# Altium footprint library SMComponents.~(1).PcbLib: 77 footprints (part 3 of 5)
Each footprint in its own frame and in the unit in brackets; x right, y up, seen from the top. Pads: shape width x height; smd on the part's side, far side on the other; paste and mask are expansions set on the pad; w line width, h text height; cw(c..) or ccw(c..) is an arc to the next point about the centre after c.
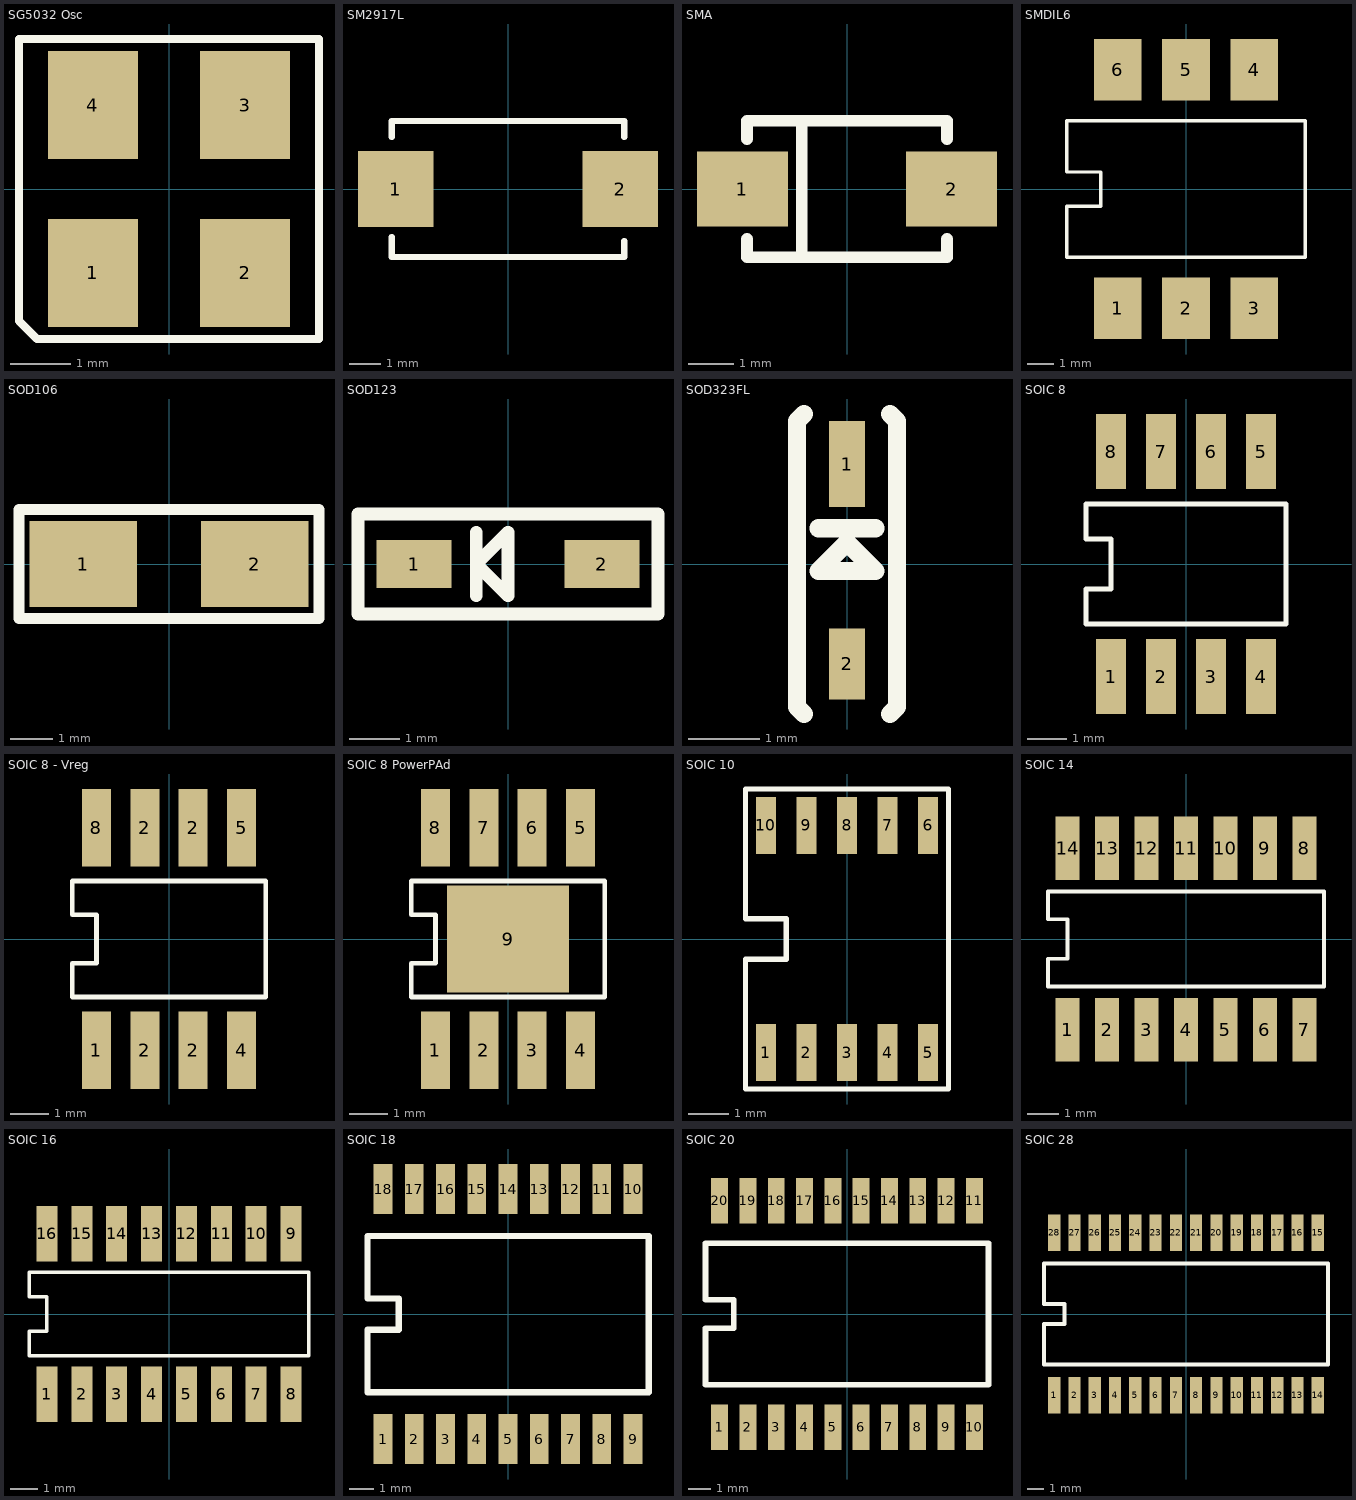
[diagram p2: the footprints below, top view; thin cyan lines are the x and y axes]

## SG5032 Osc [mm] "Epsom SG5032 oscilator"
height 1.5
pads (4):
  rect 1.5x1.8 smd: 1(-1.27,-1.4) 2(1.27,-1.4) 3(1.27,1.4) 4(-1.27,1.4)
Top Overlay:
  lines w0.127: -2.5,-2.2 -2.2,-2.5 2.5,-2.5 2.5,2.5 -2.5,2.5 -2.5,-2.2

## SM2917L [mm] "2917 for hand soldering"
pads (2):
  rect 2.4x2.4 smd: 1(-3.556,0) 2(3.556,0)
Top Overlay:
  lines w0.2: -3.683,-1.524 -3.683,-2.159 3.683,-2.159 3.683,-1.651 ; -3.683,1.651 -3.683,2.159 3.683,2.159 3.683,1.651

## SMA [mm] "SMA Diode"
height 2.65
pads (2):
  rect 2x1.65 smd: 1(-2.3,0) 2(2.3,0)
Top Overlay:
  lines w0.254: -2.2,-1.1 -2.2,-1.5 2.2,-1.5 2.2,-1.1 ; -2.2,1.1 -2.2,1.5 2.2,1.5 2.2,1.1 ; -1,-1.5 -1,1.5

## SMDIL6 [mil] "DIL6 modified to be SM"
height 200
pads (6):
  rect 70x90 smd: 1(-100,-175) 2(0,-175) 3(100,-175) 4(100,175) 5(0,175) 6(-100,175)
Top Overlay:
  lines w5: -175,-100 175,-100 175,100 -175,100 -175,25 -125,25 -125,-25 -175,-25 -175,-100

## SOD106 [mm] "SOD106 (also SOD123 etc)"
height 2
pads (2):
  rect 2.5x2 smd: 1(-2,0) 2(2,0)
Top Overlay:
  lines w0.254: -3.5,-1.27 -3.5,1.27 3.5,1.27 3.5,-1.27 -3.5,-1.27

## SOD123 [mm] "SOD123 Diode (500mW Zener etc)"
height 2
pads (2):
  rect 1.5x0.95 smd: 1(-1.875,0) 2(1.875,0)
Top Overlay:
  lines w0.254: -0.635,-0.635 -0.635,0.635 ; -3,-1 3,-1 3,1 -3,1 -3,-1 ; -0.635,0 0,-0.635 0,0.635 -0.635,0

## SOD323FL [mm]
height 1.1
pads (2):
  rect 0.5x1.2 smd: 1(0,1.4)
  rect 0.5x1 smd: 2(0,-1.4)
Top Overlay:
  lines w0.254: -0.6,-2.1 -0.7,-2 -0.7,2 -0.6,2.1 ; -0.4,0.5 0.4,0.5 ; 0.6,2.1 0.7,2 0.7,-2 0.6,-2.1 ; -0.6,2.1 -0.6,2.1 ; 0.6,-2.1 0.6,-2.1 ; -0.4,-0.1 0.4,-0.1 0,0.3 -0.4,-0.1

## SOIC 8 [mil] "SOIC 8"
height 70.87
pads (8):
  rect 30x75 smd: 1(-75,-112.5) 2(-25,-112.5) 3(25,-112.5) 4(75,-112.5) 5(75,112.5) 6(25,112.5) 7(-25,112.5) 8(-75,112.5)
Top Overlay:
  lines w5: -100,-60 -100,-25 -75,-25 -75,25 -100,25 -100,60 100,60 100,-60 -100,-60

## SOIC 8 - Vreg [mil] "SOIC 8 Special for 78Lxx and 79lXX"
height 70.87
pads (8):
  rect 30x80 smd: 1(-75,-115) 2(-25,-115) 2(-25,115) 2(25,-115) 2(25,115) 4(75,-115) 5(75,115) 8(-75,115)
Top Overlay:
  lines w5: -100,-60 -100,-25 -75,-25 -75,25 -100,25 -100,60 100,60 100,-60 -100,-60

## SOIC 8 PowerPAd [mil] "SOIC 8 with pad under device (heatsink)"
height 70.87
pads (9):
  rect 30x80 smd: 1(-75,-115) 2(-25,-115) 3(25,-115) 4(75,-115) 5(75,115) 6(25,115) 7(-25,115) 8(-75,115)
  rect 125.98x110.24 smd: 9(0,0)
Top Overlay:
  lines w5: -100,-60 100,-60 100,60 -100,60 -100,25 -75,25 -75,-25 -100,-25 -100,-60

## SOIC 10 [mm] "SOIC 10"
height 1.75
pads (10):
  rect 0.5x1.4 smd: 1(-2,-2.8) 2(-1,-2.8) 3(0,-2.8) 4(1,-2.8) 5(2,-2.8) 6(2,2.8) 7(1,2.8) 8(0,2.8) 9(-1,2.8) 10(-2,2.8)
Top Overlay:
  lines w0.127: -2.5,-3.7 -2.5,-0.5 -1.5,-0.5 -1.5,0.5 -2.5,0.5 -2.5,3.7 2.5,3.7 2.5,-3.7 -2.5,-3.7

## SOIC 14 [mil] "SOIC 14"
height 70.87
pads (14):
  rect 30x80 smd: 1(-150,-115) 2(-100,-115) 3(-50,-115) 4(0,-115) 5(50,-115) 6(100,-115) 7(150,-115) 8(150,115) 9(100,115) 10(50,115) 11(0,115) 12(-50,115) 13(-100,115) 14(-150,115)
Top Overlay:
  lines w5: -175,-60 175,-60 175,60 -175,60 -175,25 -150,25 -150,-25 -175,-25 -175,-60

## SOIC 16 [mil] "SOIC 16"
height 70.87
pads (16):
  rect 30x80 smd: 1(-175,-115) 2(-125,-115) 3(-75,-115) 4(-25,-115) 5(25,-115) 6(75,-115) 7(125,-115) 8(175,-115) 9(175,115) 10(125,115) 11(75,115) 12(25,115) 13(-25,115) 14(-75,115) 15(-125,115) 16(-175,115)
Top Overlay:
  lines w5: -200,-60 -200,-25 -175,-25 -175,25 -200,25 -200,60 200,60 200,-60 -200,-60

## SOIC 18 [mil] "SOIC 18"
height 70.87
pads (18):
  rect 30x80 smd: 1(-200,-200) 2(-150,-200) 3(-100,-200) 4(-50,-200) 5(0,-200) 6(50,-200) 7(100,-200) 8(150,-200) 9(200,-200) 10(200,200) 11(150,200) 12(100,200) 13(50,200) 14(0,200) 15(-50,200) 16(-100,200) 17(-150,200) 18(-200,200)
Top Overlay:
  lines w10: -225,-125 225,-125 225,125 -225,125 -225,25 -175,25 -175,-25 -225,-25 -225,-125

## SOIC 20 [mil] "SOIC 20"
height 70.87
pads (20):
  rect 30x80 smd: 1(-225,-200) 2(-175,-200) 3(-125,-200) 4(-75,-200) 5(-25,-200) 6(25,-200) 7(75,-200) 8(125,-200) 9(175,-200) 10(225,-200) 11(225,200) 12(175,200) 13(125,200) 14(75,200) 15(25,200) 16(-25,200) 17(-75,200) 18(-125,200) 19(-175,200) 20(-225,200)
Top Overlay:
  lines w10: -250,-125 -250,-25 -200,-25 -200,25 -250,25 -250,125 250,125 250,-125 -250,-125

## SOIC 28 [mil] "SOIC 28"
height 70.87
pads (28):
  rect 30x90 smd: 1(-325,-200) 2(-275,-200) 3(-225,-200) 4(-175,-200) 5(-125,-200) 6(-75,-200) 7(-25,-200) 8(25,-200) 9(75,-200) 10(125,-200) 11(175,-200) 12(225,-200) 13(275,-200) 14(325,-200) 15(325,200) 16(275,200) 17(225,200) 18(175,200) 19(125,200) 20(75,200) 21(25,200) 22(-25,200) 23(-75,200) 24(-125,200) 25(-175,200) 26(-225,200) 27(-275,200) 28(-325,200)
Top Overlay:
  lines w10: -350,-125 -350,-25 -300,-25 -300,25 -350,25 -350,125 350,125 350,-125 -350,-125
